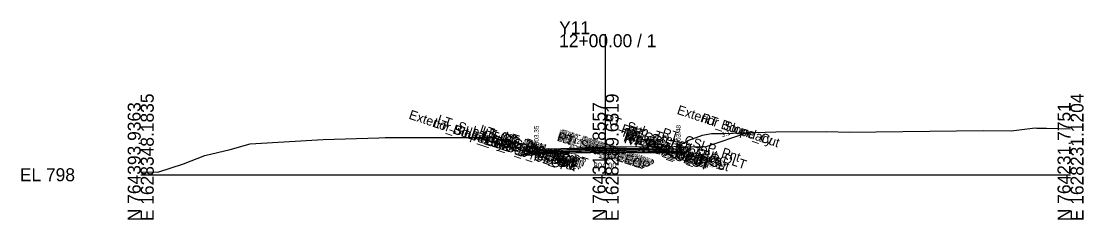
# Model space of a CAD drawing. Extents: x -26 to 203, y -10 to 6017.
# Drawn here: x -25.7 to 202.8, y 3990.3 to 4033 of the extents above; entities that cross this region are included whole.
import ezdxf

# ---------------------------------------------------------------- set-up
doc = ezdxf.new("R2010")
doc.units = 0
for name, color, linetype in [('Default', 7, 'Continuous'), ('Exist Cross Section Cell', 7, 'Continuous'), ('Exist XS Center Line Elevation Label', 7, 'Continuous'), ('Exist XS Ground Line', 7, 'Continuous'), ('Prop CMT Conc Surface', 7, 'Continuous'), ('Prop CMT Concrete Structures', 7, 'Continuous'), ('Prop CMT Pvmt Course 1', 7, 'Continuous'), ('Prop CMT Pvmt Course 1 CG', 7, 'Continuous'), ('Prop CMT Pvmt Course 2', 7, 'Continuous'), ('Prop CMT Pvmt Course 3', 7, 'Continuous'), ('Prop CMT Pvmt Surface', 7, 'Continuous'), ('Prop CMT Pvmt Wedge Surface 1', 7, 'Continuous'), ('Prop CMT Pvmt Wedge Surface 2', 7, 'Continuous'), ('Prop CMT Pvmt Wedge Surface 3', 7, 'Continuous'), ('Prop CMT Slope Grass', 7, 'Continuous'), ('Prop CMT Subgrade Earthwork', 7, 'Continuous'), ('Prop XS Hydro Elevations', 7, 'Continuous'), ('Prop XS SE Text', 7, 'Continuous'), ('Prop XS Side Slope Text', 7, 'Continuous'), ('Scratch_Level_0', 7, 'Continuous')]:
    doc.layers.add(name, color=color, linetype=linetype)

msp = doc.modelspace()

# ---------------------------------------------------------------- linework, layer by layer
at = {"layer": 'Exist Cross Section Cell'}
for p, q in [((100, 4000), (100, 4030.24)), ((0, 4000), (100, 4000)), ((100, 4000), (200, 4000))]:
    msp.add_line(p, q, dxfattribs=at)
at = {"layer": 'Exist XS Ground Line'}
msp.add_lwpolyline([(0, 4000.65), (3.69, 4000.53), (9.2, 4002.38), (13.82, 4004.12), (19.23, 4005.42), (23.51, 4006.62), (39.24, 4007.59), (51.23, 4007.97), (52.57, 4008), (59.49, 4008.01), (74.79, 4008.03), (75.65, 4008.02), (79.08, 4007.12), (82.45, 4006.68), (85.41, 4005.37), (87.82, 4005.08), (91.64, 4005.44), (96.23, 4005.9), (100, 4006), (103.26, 4006.09), (114.2, 4006.03), (115.22, 4006.18), (116.13, 4006.41), (117.92, 4007.43), (120.84, 4008.51), (122.76, 4008.84), (125.13, 4008.91), (136.64, 4009.25), (147.5, 4009.32), (152.49, 4009.15), (181.21, 4009.49), (187.25, 4009.46), (192.36, 4010.08), (192.75, 4010.05), (194.85, 4010.04), (200, 4009.85)], dxfattribs=at)
at = {"layer": 'Prop CMT Conc Surface'}
for points in [[(85.12, 4005.35), (85.12, 4005.85), (84.62, 4005.85)], [(87.12, 4005.48), (85.12, 4005.35)], [(113.63, 4005.59), (115.63, 4005.48)], [(115.63, 4005.48), (115.63, 4005.98), (116.13, 4005.98)]]:
    msp.add_lwpolyline(points, dxfattribs=at)
at = {"layer": 'Prop CMT Concrete Structures'}
for points in [[(87.12, 4005.48), (85.12, 4005.35), (85.12, 4005.85), (84.62, 4005.85)], [(84.62, 4005.85), (84.62, 4004.83), (87.12, 4004.89)], [(87.12, 4004.89), (87.12, 4005.48)], [(113.63, 4005.59), (115.63, 4005.48), (115.63, 4005.98), (116.13, 4005.98)], [(116.13, 4005.98), (116.13, 4004.97), (113.63, 4005.01)], [(113.63, 4005.01), (113.63, 4005.59)]]:
    msp.add_lwpolyline(points, dxfattribs=at)
at = {"layer": 'Prop CMT Pvmt Course 1'}
for points in [[(100, 4005.8), (87.12, 4005.48)], [(87.12, 4005.23), (100, 4005.55)], [(87.12, 4005.48), (87.12, 4005.23)], [(100, 4005.55), (100, 4005.8)], [(100, 4005.8), (113.63, 4005.59)], [(100, 4005.55), (100, 4005.8)], [(113.63, 4005.34), (100, 4005.55)], [(113.63, 4005.59), (113.63, 4005.34)]]:
    msp.add_lwpolyline(points, dxfattribs=at)
msp.add_lwpolyline([(100, 4005.55), (100, 4005.67), (100, 4005.67), (100, 4005.55)], close=True, dxfattribs=at)
msp.add_lwpolyline([(100, 4005.55), (100, 4005.67), (100, 4005.67), (100, 4005.55)], close=True, dxfattribs=at)
at = {"layer": 'Prop CMT Pvmt Course 1 CG'}
for points in [[(87.12, 4004.89), (84.12, 4004.82), (83.78, 4004.48)], [(83.78, 4004.48), (87.12, 4004.56)], [(87.12, 4004.56), (87.12, 4004.89)], [(113.63, 4005.01), (116.63, 4004.97), (116.97, 4004.63)], [(113.63, 4004.68), (113.63, 4005.01)], [(116.97, 4004.63), (113.63, 4004.68)]]:
    msp.add_lwpolyline(points, dxfattribs=at)
at = {"layer": 'Prop CMT Pvmt Course 2'}
for points in [[(100, 4005.55), (87.12, 4005.23)], [(87.12, 4005.23), (87.12, 4004.89)], [(87.12, 4004.89), (100, 4005.21)], [(100, 4005.21), (100, 4005.55)], [(100, 4005.21), (100, 4005.55)], [(100, 4005.55), (113.63, 4005.34)], [(100, 4005.55), (100, 4005.55)], [(100, 4005.55), (100, 4005.55)], [(113.63, 4005.01), (100, 4005.21)], [(113.63, 4005.34), (113.63, 4005.01)]]:
    msp.add_lwpolyline(points, dxfattribs=at)
msp.add_lwpolyline([(100, 4005.55), (100, 4005.21), (100, 4005.21)], close=True, dxfattribs=at)
msp.add_lwpolyline([(100, 4005.55), (100, 4005.21), (100, 4005.21)], close=True, dxfattribs=at)
at = {"layer": 'Prop CMT Pvmt Course 3'}
for points in [[(100, 4005.21), (87.12, 4004.89)], [(87.12, 4004.89), (87.12, 4004.56)], [(87.12, 4004.56), (100, 4004.88)], [(100, 4004.88), (100, 4005.21)], [(100, 4005.21), (113.63, 4005.01)], [(100, 4004.88), (100, 4005.21)], [(100, 4005.21), (100, 4005.21), (100, 4004.88), (100, 4004.88)], [(100, 4004.88), (100, 4005.21)], [(100, 4005.21), (100, 4005.21), (100, 4004.88), (100, 4004.88)], [(100, 4004.88), (100, 4005.21)], [(113.63, 4004.68), (100, 4004.88)], [(113.63, 4005.01), (113.63, 4004.68)]]:
    msp.add_lwpolyline(points, dxfattribs=at)
at = {"layer": 'Prop CMT Pvmt Surface'}
for points in [[(100, 4005.8), (87.12, 4005.48)], [(100, 4005.8), (113.63, 4005.59)]]:
    msp.add_lwpolyline(points, dxfattribs=at)
at = {"layer": 'Prop CMT Pvmt Wedge Surface 1'}
for points in [[(100, 4005.8), (100, 4005.55), (100, 4005.55)], [(100, 4005.8), (100, 4005.55), (100, 4005.55)], [(100, 4005.55), (100, 4005.67)], [(100, 4005.55), (100, 4005.67)]]:
    msp.add_lwpolyline(points, dxfattribs=at)
at = {"layer": 'Prop CMT Pvmt Wedge Surface 2'}
for points in [[(100, 4005.8), (100, 4005.55)], [(100, 4005.8), (100, 4005.55)], [(100, 4005.55), (100, 4005.55)], [(100, 4005.55), (100, 4005.55)]]:
    msp.add_lwpolyline(points, dxfattribs=at)
at = {"layer": 'Prop CMT Pvmt Wedge Surface 3'}
for points in [[(100, 4005.8), (100, 4005.21)], [(100, 4005.8), (100, 4005.21)], [(100, 4005.21), (100, 4005.21)], [(100, 4005.21), (100, 4005.21)]]:
    msp.add_lwpolyline(points, dxfattribs=at)
at = {"layer": 'Prop CMT Slope Grass'}
for points in [[(116.13, 4005.98), (121.63, 4006.09), (130.56, 4009.07)], [(84.62, 4005.85), (79.12, 4005.96), (72.89, 4008.03)]]:
    msp.add_lwpolyline(points, dxfattribs=at)
at = {"layer": 'Prop CMT Subgrade Earthwork'}
for points in [[(87.12, 4004.56), (83.78, 4004.48), (82.36, 4005.89)], [(100, 4004.88), (87.12, 4004.56)], [(100, 4004.88), (113.63, 4004.68)], [(113.63, 4004.68), (116.97, 4004.63), (118.37, 4006.03)]]:
    msp.add_lwpolyline(points, dxfattribs=at)

# ---------------------------------------------------------------- texts
at = {"layer": 'Default'}
msp.add_text('-', height=0.0001, dxfattribs=at).set_placement((0, 4000))
at = {"layer": 'Exist Cross Section Cell'}
for s, p in [('Y11', (90, 4030.24)), ('12+00.00 / 1', (90, 4027.44)), ('EL 798', (-26, 3998.6))]:
    msp.add_text(s, height=2.8, dxfattribs=at).set_placement(p)
for s, p in [('N 764393.9363', (0, 3990)), ('E 1628348.1835', (2.8, 3990)), ('N 764312.8557', (100, 3990)), ('E 1628289.6519', (102.8, 3990)), ('N 764231.7751', (200, 3990)), ('E 1628231.1204', (202.8, 3990))]:
    msp.add_text(s, height=2.8, rotation=90, dxfattribs=at).set_placement(p)
at = {"layer": 'Exist XS Center Line Elevation Label'}
msp.add_text('804.00', height=1.2, dxfattribs=at).set_placement((97.43, 4001.4))
at = {"layer": 'Prop XS Hydro Elevations'}
for s, p in [('803.35', (85.62, 4006.35)), ('803.48', (116.13, 4006.48))]:
    msp.add_text(s, height=1, rotation=90, dxfattribs=at).set_placement(p)
at = {"layer": 'Prop XS SE Text'}
for s, rotation, p in [('0.025', 1.4321, (91.8, 4006.59)), ('0.015', 359.1406, (105.22, 4006.72))]:
    msp.add_text(s, height=1, rotation=rotation, dxfattribs=at).set_placement(p)
at = {"layer": 'Prop XS Side Slope Text'}
for rotation, p in [(341.5668, (75.49, 4007.96)), (18.4332, (125.11, 4008.04))]:
    msp.add_text('3:1', height=1, rotation=rotation, dxfattribs=at).set_placement(p)
at = {"layer": 'Scratch_Level_0'}
for s, p in [('Exterior Boundary', (57.53, 4012.1)), ('RT_Sub_Trench_Out_DLT', (99.57, 4011.24)), ('Exterior Boundary', (115.2, 4013.14)), ('RT_Slope_Cut', (120.37, 4011.41)), ('LT_Slope_Cut', (62.75, 4010.36)), ('LT_Sub_Trench_Out_DLT', (63.61, 4011.09)), ('LT_CG_Top_Face', (72.72, 4008.93)), ('RT_CG_Top_Face', (103.18, 4009.08)), ('LT_CSLP_Pnt', (69.48, 4008.11)), ('LT_CG1_Shelf_Out', (71.05, 4008.12)), ('LT_CG_Top_BOC', (73.19, 4008.6)), ('LT_CG_Bot_BOC', (73.22, 4007.58)), ('LT_CG_Top_Gut', (73.64, 4008.12)), ('LT_Sub_OEOP', (74.08, 4006.65)), ('LT_CG_Bot_IE', (77.24, 4007.13)), ('LT_Sub_OEOT', (77.39, 4006.75)), ('LT_PV2_OEOT', (77.48, 4007.38)), ('LT_PV3_OEOT', (77.48, 4007.05)), ('LT_PV1_OEOT', (78.02, 4007.46)), ('RT_Sub_OEEOP', (89.41, 4007.36)), ('LT_Sub_OEEOP', (89.45, 4007.34)), ('RT_PV2_OEEOP', (89.49, 4008)), ('RT_PV3_OEEOP', (89.49, 4007.66)), ('LT_PV2_OEEOP', (89.54, 4007.98)), ('LT_PV3_OEEOP', (89.54, 4007.65)), ('RT_Sub_IEEOP', (90.02, 4007.15)), ('RT_PV1_OEEOP', (90.03, 4007.94)), ('LT_Sub_IEEOP', (90.06, 4007.14)), ('LT_PV1_OEEOP', (90.08, 4007.93)), ('RT_PV2_IEEOP', (90.11, 4007.79)), ('RT_PV3_IEEOP', (90.11, 4007.46)), ('LT_PV2_IEEOP', (90.15, 4007.78)), ('LT_PV3_IEEOP', (90.15, 4007.44)), ('RT_PV1_IEEOP', (90.65, 4007.74)), ('LT_PV1_IEEOP', (90.69, 4007.72)), ('RT_CG1_Shelf_Out', (103.51, 4008.28)), ('RT_CG_Bot_IE', (103.7, 4007.27)), ('RT_Sub_OEOT', (103.86, 4006.88)), ('RT_PV2_OEOT', (103.95, 4007.52)), ('RT_PV3_OEOT', (103.95, 4007.18)), ('RT_CG_Top_Gut', (104.11, 4008.27)), ('RT_PV1_OEOT', (104.48, 4007.59)), ('RT_CG_Top_BOC', (104.66, 4008.75)), ('RT_CG_Bot_BOC', (104.68, 4007.73)), ('RT_Sub_OEOP', (107.23, 4006.82)), ('RT_CSLP_Pnt', (111.95, 4008.27)), ('Sub_PGL', (93.81, 4005.89)), ('PV2_PGL', (93.9, 4006.53)), ('PV3_PGL', (93.9, 4006.19)), ('PV1_PGL', (94.44, 4006.6))]:
    msp.add_text(s, height=2, rotation=341.5651, dxfattribs=at).set_placement(p)

doc.saveas('drawing.dxf')
